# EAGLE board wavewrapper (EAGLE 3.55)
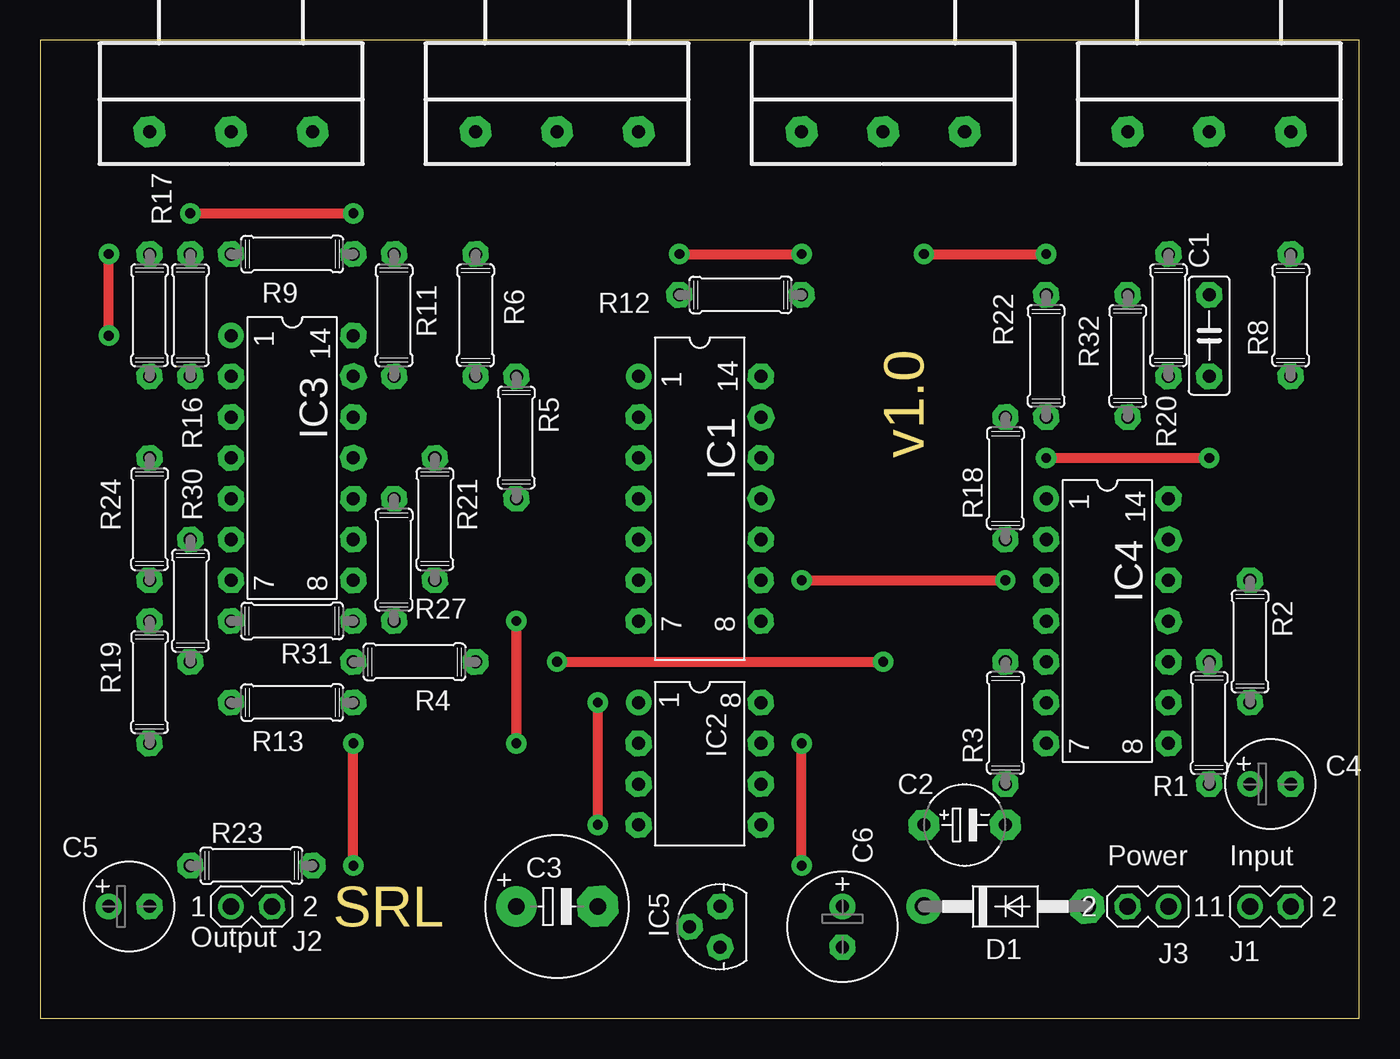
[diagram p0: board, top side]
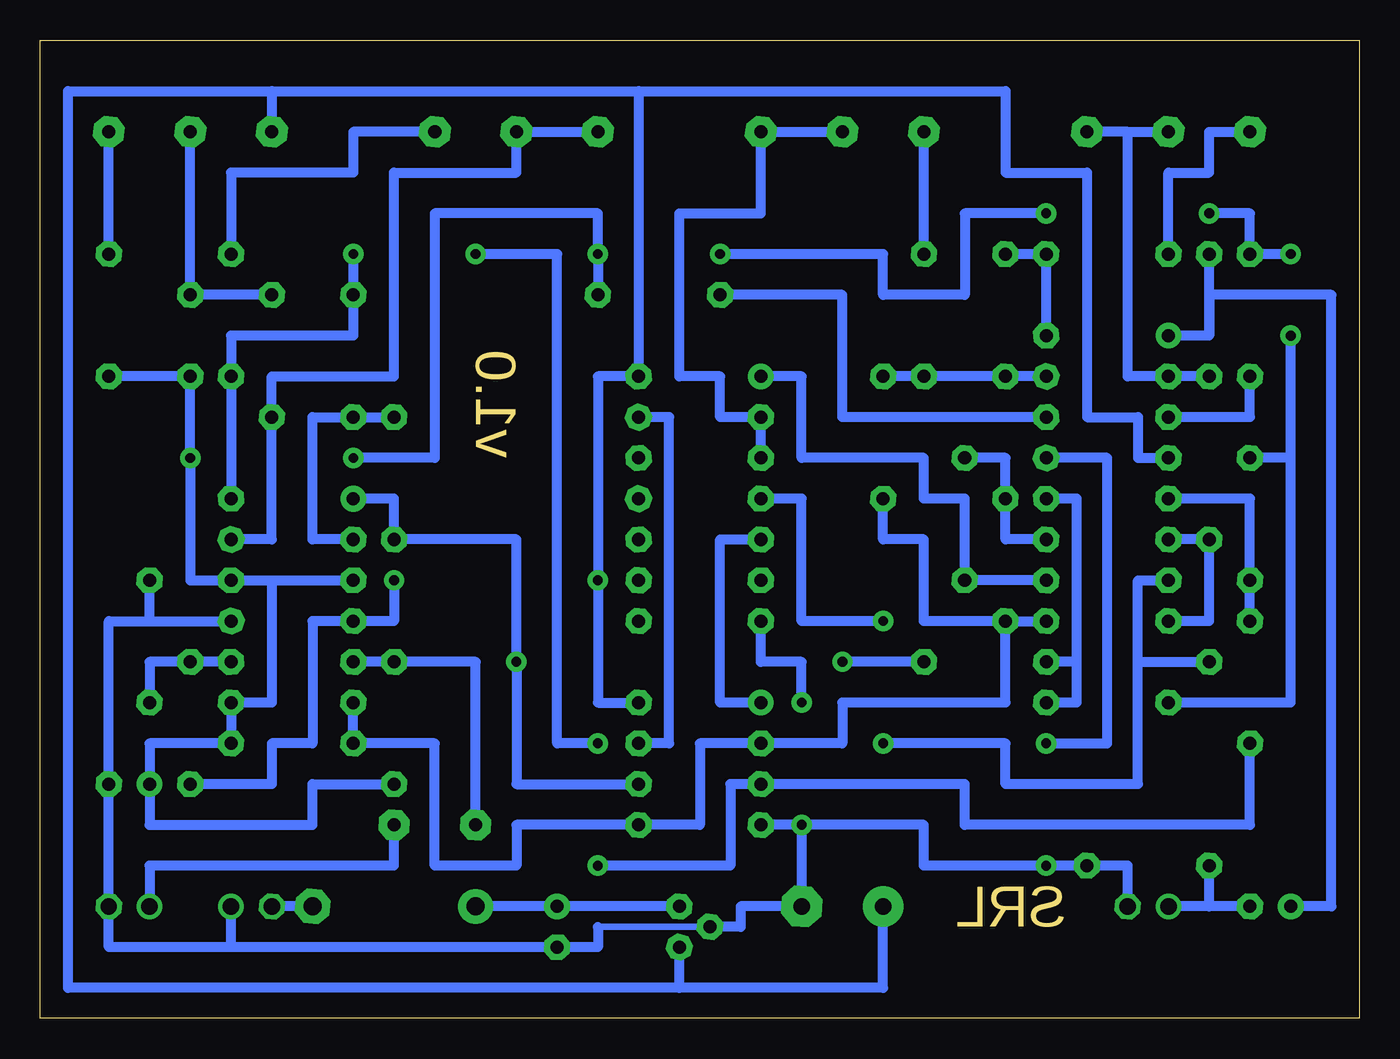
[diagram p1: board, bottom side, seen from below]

Size 82.22 x 60.95 mm. Coordinates in mm from the lower left corner, seen from the top.
Outline: 0,0 82.22,0 82.22,60.95 0,60.95 0,0
Copper layers used: Top, Bottom

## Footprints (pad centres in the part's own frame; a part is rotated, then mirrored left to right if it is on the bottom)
B2,5 = drill 0.813 pad 1.6 octagon:  -2.54,0;  2.54,0
-5 = drill 0.813 pad 1.905 octagon:  -2.54,0;  2.54,0
-8,5 = drill 1.016 pad 2.54 round:  -2.54,0 | drill 1.016 pad 2.54 octagon:  2.54,0
,5-6 = drill 0.813 pad 1.6 octagon:  1.27,0 | drill 0.813 pad 1.6 round:  -1.27,0
,5-7 = drill 0.813 pad 1.6 octagon:  1.27,0 | drill 0.813 pad 1.6 round:  -1.27,0
41-10 = drill 1.118 pad 2.159 octagon:  5.08,0 | drill 1.118 pad 2.159 round:  -5.08,0
L14 = drill 0.813 pad 1.6 round:  -7.62,-3.81 | drill 0.813 pad 1.6 octagon:  -5.08,-3.81;  -2.54,-3.81;  0,-3.81;  2.54,-3.81;  5.08,-3.81;  7.62,-3.81;  7.62,3.81;  5.08,3.81;  2.54,3.81;  0,3.81;  -2.54,3.81;  -5.08,3.81;  -7.62,3.81
L08 = drill 0.813 pad 1.6 round:  -3.81,-3.81 | drill 0.813 pad 1.6 octagon:  -1.27,-3.81;  1.27,-3.81;  3.81,-3.81;  3.81,3.81;  1.27,3.81;  -1.27,3.81;  -3.81,3.81
LXX = drill 0.813 pad 1.6 octagon:  -1.27,0;  0,1.905;  1.27,0
02-1 = drill 1.016 pad 1.6 round:  -1.27,0 | drill 1.016 pad 1.6 octagon:  1.27,0
H6-H = drill 0.813 pad 1.93 octagon:  0,0;  -5.08,0;  5.08,0
07/7 = drill 0.813 pad 1.6 octagon:  -3.81,0;  3.81,0

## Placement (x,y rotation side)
C1  100n  [B2,5]  72.86,42.54 90 top
C2  1u  [-5]  57.62,12.06 0 top
C3  470u/16V  [-8,5]  32.22,6.98 0 top
C4  47u  [,5-6]  76.67,14.6 0 top
C5  1u  [,5-6]  5.55,6.98 0 top
C6  100u/25V  [,5-7]  50,5.71 270 top
D1  1N4004  [41-10]  60.16,6.98 0 top
IC1  4066  [L14]  41.11,32.38 270 top
IC2  TL072P  [L08]  41.11,15.87 270 top
IC3  TL074N  [L14]  15.71,34.92 270 top
IC4  TL074N  [L14]  66.51,24.76 270 top
IC5  78L15  [LXX]  42.38,5.71 90 top
J1  MA02-1  [02-1]  76.67,6.98 0 top
J2  MA02-1  [02-1]  13.17,6.98 0 top
J3  MA02-1  [02-1]  69.05,6.98 180 top
P1  10k  [H6-H]  72.86,55.24 180 top
P2  100k  [H6-H]  52.54,55.24 180 top
P3  1M log  [H6-H]  32.22,55.24 180 top
P4  10k  [H6-H]  11.9,55.24 180 top
R1  100k  [07/7]  72.86,18.41 270 top
R2  100k  [07/7]  75.4,23.49 270 top
R3  100k  [07/7]  60.16,18.41 90 top
R4  10k  [07/7]  23.33,22.22 0 top
R5  10k  [07/7]  29.68,36.19 270 top
R6  4k7  [07/7]  27.14,43.81 90 top
R8  220  [07/7]  77.94,43.81 90 top
R9  1k  [07/7]  15.71,47.62 0 top
R11  10k  [07/7]  22.06,43.81 270 top
R12  3k3  [07/7]  43.65,45.08 0 top
R13  10k  [07/7]  15.71,19.68 0 top
R16  10k  [07/7]  9.36,43.81 270 top
R17  4k7  [07/7]  6.82,43.81 270 top
R18  100k  [07/7]  60.16,33.65 90 top
R19  10k  [07/7]  6.82,20.95 270 top
R20  220  [07/7]  70.32,43.81 90 top
R21  10k  [07/7]  24.6,31.11 270 top
R22  100k  [07/7]  62.7,41.27 90 top
R23  100k  [07/7]  13.17,9.52 0 top
R24  10k  [07/7]  6.82,31.11 270 top
R27  10k  [07/7]  22.06,28.57 90 top
R30  10k  [07/7]  9.36,26.03 270 top
R31  10k  [07/7]  15.71,24.76 180 top
R32  100k  [07/7]  67.78,41.27 270 top

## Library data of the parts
C1 = CAP
C2-C6 = POLCAP
D1 = DIODE
IC1 = 40XX
IC2-IC4 = LINEAR
IC5 = V-REG
J1-J3 = CON-LSTB
P1-P4 = pots
R1-R6 R8 R9 R11-R13 R16-R24 R27 R30-R32 = R

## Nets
+15V: C3. IC1. IC2. IC3. IC4. IC5. P1. R1.
GND: C3. C4. C6. IC1. IC2. IC3. IC4. IC5. J1. J2. J3. R2. R23.
N$1: IC3. P4. R16.
N$2: IC4. R1. R2.
N$3: C2. IC4. R3.
N$4: P1. R8.
N$5: C5. IC3. R16.
N$6: IC3. R17.
N$7: C1. P1. R32.
N$8: IC3. R9. R11.
N$9: IC3. R12.
N$10: IC3. R5. R6. R11.
N$11: IC2. IC4. R19. R20. R22.
N$12: P3. R6.
N$13: IC4. P2. R32.
N$14: IC1. P3.
N$15: IC3. R19. R24.
N$16: IC4. R18. R22.
N$17: IC2. IC4. R4. R18.
N$18: IC2. IC4. R5. R27. R31.
N$19: C5. J2. R23.
N$20: IC1. IC3. R21.
N$21: IC3. R4. R13.
N$22: IC1. IC2.
N$23: IC1. IC2.
N$24: P4. R9.
N$25: IC1. IC3. R30.
N$26: C2. J1.
N$27: P2. R20.
N$28: C6. D1. IC5.
N$29: IC3. R30. R31.
N$30: IC3. R21. R27.
N$31: D1. J3.
V1: C1. C4. IC4. R3. R8. R12. R13. R17. R24.

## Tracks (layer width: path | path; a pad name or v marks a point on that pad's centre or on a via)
+15V  (via drill 0.61 pad 1.27)
  Top 0.61: v47.46,27.3 v60.16,27.3
  Bottom 0.61: 67.78,57.78 P1. | 67.78,57.78 44.92,57.78 | R1. 67.78,14.6 67.78,17.14 65.24,17.14 65.24,24.76 62.7,24.76 60.16,24.76 v60.16,27.3 | 44.92,57.78 IC1. 47.46,40 v47.46,27.3 47.46,19.68 IC2. | 29.68,6.98 29.68,1.9 42.38,1.9 | 11.9,34.92 13.8,34.92 13.8,37.46 16.98,37.46 16.98,52.7 22.06,52.7 22.06,57.78 44.92,57.78 | 42.38,1.9 42.38,4.44 | 42.38,1.9 80.48,1.9 80.48,57.78 67.78,57.78
GND  (via drill 0.61 pad 1.27)
  Top 0.61: v34.76,12.06 v34.76,19.68 | v19.52,9.52 v19.52,17.14
  Bottom 0.406: 40.48,5.71 47.46,5.71
  Bottom 0.61: 75.4,24.76 70.32,24.76 | 75.4,24.76 75.4,27.3 | 75.4,24.76 77.94,24.76 77.94,14.6 J1. 77.94,4.44 70.32,4.44 | 40.48,5.71 38.57,5.71 38.57,6.98 C3. v34.76,12.06 | 47.46,5.71 47.46,4.44 50,4.44 70.32,4.44 | v34.76,12.06 37.3,12.06 v34.76,12.06 | v34.76,19.68 34.76,22.22 37.3,22.22 37.3,24.76 | 70.32,4.44 70.32,6.98 | 19.52,34.92 15.71,34.92 15.71,17.14 v19.52,17.14 | J2. 14.44,9.52 R23. v19.52,9.52 27.14,9.52 27.14,12.06 v34.76,12.06
N$1
  Bottom 0.61: 14.44,55.24 14.44,40 11.9,40 R16. | 14.44,55.24 16.98,55.24 | 14.44,55.24 11.9,55.24
N$2
  Bottom 0.61: 70.32,22.22 72.86,22.22 75.4,22.22 R2.
N$3
  Bottom 0.61: 62.7,22.22 R3. 55.08,22.22 55.08,12.06
N$4
  Bottom 0.61: R8. 77.94,55.24
N$5
  Bottom 0.61: 9.36,42.54 9.36,47.62 | 9.36,42.54 11.9,42.54 | 9.36,42.54 9.36,45.08 1.74,45.08 1.74,6.98 C5.
N$6
  Bottom 0.61: 11.9,37.46 6.82,37.46 R17.
N$7
  Bottom 0.61: 72.86,55.24 C1. 67.78,45.08
N$8
  Bottom 0.61: IC3. R9. 22.06,47.62
N$9
  Bottom 0.61: 39.84,45.08 32.22,45.08 32.22,37.46 19.52,37.46
N$10
  Bottom 0.61: 19.52,40 R11. 27.14,40 29.68,40
N$11  (via drill 0.61 pad 1.27)
  Top 0.61: v47.46,9.52 v47.46,17.14 | v55.08,47.62 v62.7,47.62
  Bottom 0.61: IC4. 70.32,40 70.32,42.54 62.7,42.54 R22. v62.7,47.62 | v47.46,9.52 39.2,9.52 39.2,14.6 37.3,14.6 24.6,14.6 24.6,12.06 6.82,12.06 R19. | v47.46,17.14 50,17.14 50,47.62 v55.08,47.62
N$12
  Bottom 0.61: R6. P3.
N$13
  Bottom 0.61: 70.32,29.84 67.78,29.84 R32. 67.78,40 60.16,40 60.16,52.7 52.54,52.7 52.54,55.24 P2.
N$14
  Bottom 0.61: 37.3,34.92 37.3,37.46 39.84,37.46 39.84,40 42.38,40 42.38,50.16 37.3,50.16 37.3,55.24 32.22,55.24
N$15
  Bottom 0.61: 11.9,32.38 6.82,32.38 R24. 6.82,24.76
N$16
  Bottom 0.61: 62.7,29.84 65.24,29.84 65.24,37.46 62.7,37.46 R18.
N$17  (via drill 0.61 pad 1.27)
  Top 0.61: v32.22,22.22 v52.54,22.22
  Bottom 0.61: 62.7,32.38 60.16,32.38 60.16,29.84 52.54,29.84 v52.54,22.22 52.54,14.6 44.92,14.6 | R4. v32.22,22.22
N$18
  Bottom 0.61: 62.7,19.68 62.7,17.14 57.62,17.14 57.62,9.52 52.54,9.52 52.54,12.06 44.92,12.06 41.11,12.06 41.11,17.14 37.3,17.14 32.22,17.14 32.22,19.68 22.06,19.68 22.06,24.76 | 22.06,24.76 19.52,24.76 | 22.06,24.76 19.52,24.76 | 22.06,24.76 19.52,24.76 | 22.06,24.76 27.14,24.76 27.14,29.84 29.68,29.84 R5.
N$19
  Bottom 0.61: 9.36,9.52 9.36,6.98 6.82,6.98 11.9,6.98
N$20
  Bottom 0.61: 37.3,40 34.76,40 34.76,34.92 27.14,34.92 27.14,32.38 24.6,32.38 R21. 19.52,27.3
N$21
  Bottom 0.61: 19.52,32.38 17.62,32.38 17.62,22.22 | 17.62,22.22 19.52,22.22 | R13. 17.62,19.68 17.62,22.22
N$22
  Bottom 0.61: 44.92,37.46 43.02,37.46 43.02,17.14 44.92,17.14
N$23
  Bottom 0.61: 37.3,29.84 39.84,29.84 39.84,19.68 37.3,19.68
N$24
  Bottom 0.61: P4. 9.36,55.24 9.36,52.7 11.9,52.7 11.9,47.62
N$25  (via drill 0.61 pad 1.27)
  Top 0.61: v29.68,17.14 v29.68,24.76
  Bottom 0.61: v29.68,24.76 34.76,24.76 34.76,32.38 37.3,32.38 | 11.9,27.3 13.8,27.3 13.8,22.22 | 13.8,22.22 13.8,14.6 22.06,14.6 22.06,17.14 v29.68,17.14 | 13.8,22.22 R30.
N$26
  Bottom 0.61: 75.4,6.98 75.4,9.52 60.16,9.52 C2.
N$27
  Bottom 0.61: 57.62,55.24 62.7,55.24 62.7,52.7 70.32,52.7 R20.
N$28
  Bottom 0.406: D1. C6. IC5.
  Bottom 0.61: IC5. C6. D1.
N$29
  Bottom 0.61: R31. 9.36,24.76 9.36,29.84 11.9,29.84
N$30
  Bottom 0.61: 24.6,34.92 22.06,34.92 R27. 22.06,29.84 19.52,29.84
N$31
  Bottom 0.406: 65.24,6.98 J3.
  Bottom 0.61: 65.24,6.98 J3.
V1  (via drill 0.61 pad 1.27)
  Top 0.61: v62.7,34.92 v72.86,34.92 | v39.84,47.62 v47.46,47.62 | v9.36,50.16 v19.52,50.16 | v4.28,42.54 v4.28,47.62
  Bottom 0.61: 77.94,40 72.86,40 v72.86,34.92 72.86,27.3 70.32,27.3 | 70.32,27.3 62.7,27.3 | 70.32,27.3 67.78,27.3 67.78,19.68 70.32,19.68 70.32,17.14 75.4,17.14 C4. 75.4,12.06 65.24,12.06 65.24,14.6 60.16,14.6 | v62.7,34.92 57.62,34.92 57.62,50.16 47.46,50.16 v47.46,47.62 R12. | v39.84,47.62 29.68,47.62 29.68,45.08 24.6,45.08 24.6,50.16 v19.52,50.16 | v9.36,50.16 6.82,50.16 6.82,47.62 v4.28,47.62 | 4.28,34.92 6.82,34.92 | 4.28,34.92 4.28,19.68 11.9,19.68 | 4.28,34.92 v4.28,42.54

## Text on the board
Dimension: v1.0 | SRL
tNames: Power | Input | Output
